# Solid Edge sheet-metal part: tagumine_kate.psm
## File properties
Author: Blackblade
Template: Normal.psm
Last saved by: Blackblade
Revision: 2
Application: Solid Edge
Accuracy: 0.990
Material Thickness: 1.00 mm
Bend Radius: 1.00 mm
Relief Width: 1.00 mm
Relief Length: 0.00 mm
Neutral Factor: 0.330
Minimum Arc Length: 0.10 mm
Deviational Tolerance: 0.10 mm
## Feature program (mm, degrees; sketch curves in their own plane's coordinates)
base tab "unnamed BaseTab 1"
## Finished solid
Body 1: solid body, 6 faces, 12 edges, 8 vertices.
  Faces by surface: cylinder 3, plane 3
  Edges by curve: circle 6, line 6
Bounding box of the edges (mm): 62.198 x 114.818 x 1.000, from (-130.5252, -57.8171, 0) to (-68.3271, 57.0007, 1).
Cylindrical faces by radius (mm): R80.0992 x1, R649 x2
Planar faces by outward normal: +x 1, +z 1, -z 1
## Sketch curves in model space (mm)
arc centre (67.9255, -577.5355, 0) radius 649 from (-68.3271, 57.0007, 0) through (-92.6009, 51.2986, 0) to (-116.6378, 44.6682, 0)
arc centre (-50.426, -0.4082, 0) radius 80.0992 from (-116.6378, -45.4846, 0) through (-130.5252, -0.4082, 0) to (-116.6378, 44.6682, 0)
arc centre (67.9255, 576.7191, 0) radius 649 from (-116.6378, -45.4846, 0) through (-92.6009, -52.115, 0) to (-68.3271, -57.8171, 0)
line (-68.3271, -57.8171, 0) -> (-68.3271, 57.0007, 0)
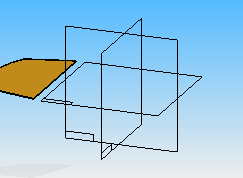
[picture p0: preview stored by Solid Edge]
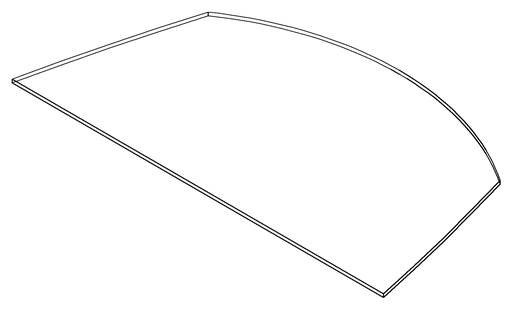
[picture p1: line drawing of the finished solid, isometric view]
